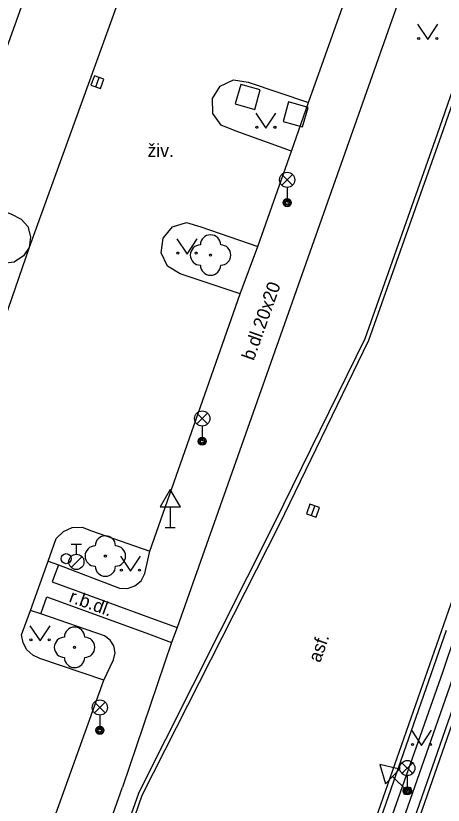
# Model space of a CAD drawing. Extents: x -598932 to -598196, y -1162207 to -1161504.
# Drawn here: x -598625.59 to -598604.5, y -1162150.78 to -1162111.78 of the extents above; entities that cross this region are included whole.
import ezdxf

# ---------------------------------------------------------------- set-up
doc = ezdxf.new("R2010")
doc.units = 0
for name, color, linetype in [('Level 22', 7, 'Continuous'), ('Level 26', 7, 'Continuous'), ('Level 27', 7, 'Continuous'), ('Level 28', 7, 'Continuous'), ('Level 33', 7, 'Continuous'), ('Level 34', 7, 'Continuous'), ('Level 36', 7, 'Continuous'), ('TM - chodniky - VP', 7, 'Continuous'), ('TM - komunikace - VP', 7, 'Continuous'), ('TM - plot dreveny_ kovovy - VP', 7, 'Continuous'), ('TM - popis povrchu', 7, 'Continuous'), ('TM - rozhrani ploch obecne - VP', 7, 'Continuous'), ('TM - svodidlo jednostranne - VP', 7, 'Continuous')]:
    doc.layers.add(name, color=color, linetype=linetype)

msp = doc.modelspace()

# ---------------------------------------------------------------- linework, layer by layer
at = {"layer": 'Level 22'}
for centre in [(-598615.98, -1162123.6), (-598621.17, -1162138.47), (-598622.69, -1162142.98)]:
    msp.add_circle(centre, 0.05, dxfattribs=at)
for centre, start, end in [((-598615.98, -1162123.1), 0, 180), ((-598616.48, -1162123.6), 90, 270), ((-598615.48, -1162123.6), 270, 90), ((-598615.98, -1162124.1), 180, 0), ((-598621.17, -1162137.97), 0, 180), ((-598621.67, -1162138.47), 90, 270), ((-598620.67, -1162138.47), 270, 90), ((-598621.17, -1162138.97), 180, 0), ((-598622.69, -1162142.48), 0, 180), ((-598623.19, -1162142.98), 90, 270), ((-598622.19, -1162142.98), 270, 90), ((-598622.69, -1162143.48), 180, 0)]:
    msp.add_arc(centre, 0.5, start, end, dxfattribs=at)
at = {"layer": 'Level 26'}
for points in [[(-598614.757, -1162116.135), (-598613.795, -1162116.407), (-598613.523, -1162115.445), (-598614.485, -1162115.173)], [(-598612.397, -1162116.995), (-598611.435, -1162117.267), (-598611.163, -1162116.305), (-598612.125, -1162116.033)]]:
    msp.add_lwpolyline(points, close=True, dxfattribs=at)
at = {"layer": 'Level 27'}
for p, q in [((-598621.643, -1162115.296), (-598621.477, -1162114.824)), ((-598611.002, -1162136.466), (-598610.838, -1162135.994))]:
    msp.add_line(p, q, dxfattribs=at)
for points in [[(-598621.408, -1162115.379), (-598621.241, -1162114.908), (-598621.712, -1162114.741), (-598621.879, -1162115.212)], [(-598610.766, -1162136.548), (-598610.602, -1162136.076), (-598611.074, -1162135.912), (-598611.238, -1162136.384)]]:
    msp.add_lwpolyline(points, close=True, dxfattribs=at)
at = {"layer": 'Level 28'}
for p, q in [((-598622.85, -1162137.885), (-598622.35, -1162137.885)), ((-598622.6, -1162138.385), (-598622.6, -1162137.885)), ((-598622.858, -1162139.032), (-598622.328, -1162138.502))]:
    msp.add_line(p, q, dxfattribs=at)
for centre, radius in [((-598623.1, -1162138.6), 0.25), ((-598622.6, -1162138.76), 0.375)]:
    msp.add_circle(centre, radius, dxfattribs=at)
at = {"layer": 'Level 33'}
for p, q in [((-598612.465, -1162120.15), (-598611.935, -1162119.62)), ((-598612.465, -1162119.62), (-598611.935, -1162120.15)), ((-598612.2, -1162120.26), (-598612.2, -1162121.01)), ((-598616.655, -1162131.94), (-598616.125, -1162131.41)), ((-598616.655, -1162131.41), (-598616.125, -1162131.94)), ((-598616.39, -1162132.05), (-598616.39, -1162132.8)), ((-598621.705, -1162146.22), (-598621.175, -1162145.69)), ((-598621.705, -1162145.69), (-598621.175, -1162146.22)), ((-598621.44, -1162146.33), (-598621.44, -1162147.08)), ((-598606.535, -1162149.21), (-598606.005, -1162148.68)), ((-598606.535, -1162148.68), (-598606.005, -1162149.21)), ((-598606.27, -1162149.32), (-598606.27, -1162150.07))]:
    msp.add_line(p, q, dxfattribs=at)
for centre, radius in [((-598612.2, -1162119.885), 0.375), ((-598612.2, -1162121.01), 0.2), ((-598612.2, -1162121.01), 0.145), ((-598612.2, -1162121.01), 0.0876), ((-598616.39, -1162131.675), 0.375), ((-598616.39, -1162132.8), 0.2), ((-598616.39, -1162132.8), 0.145), ((-598616.39, -1162132.8), 0.0876), ((-598621.44, -1162145.955), 0.375), ((-598621.44, -1162147.08), 0.2), ((-598621.44, -1162147.08), 0.145), ((-598621.44, -1162147.08), 0.0876), ((-598606.27, -1162148.945), 0.375), ((-598606.27, -1162150.07), 0.2), ((-598606.27, -1162150.07), 0.145), ((-598606.27, -1162150.07), 0.0876)]:
    msp.add_circle(centre, radius, dxfattribs=at)
at = {"layer": 'Level 34'}
for p, q in [((-598617.97, -1162136.042), (-598617.97, -1162137.06)), ((-598618.22, -1162137.06), (-598617.72, -1162137.06)), ((-598607.006, -1162149.367), (-598606.27, -1162150.07)), ((-598606.443, -1162150.251), (-598606.097, -1162149.889))]:
    msp.add_line(p, q, dxfattribs=at)
for points in [[(-598618.47, -1162136.042), (-598617.47, -1162136.042), (-598617.97, -1162135.176)], [(-598607.352, -1162149.729), (-598606.661, -1162149.005), (-598607.633, -1162148.769)]]:
    msp.add_lwpolyline(points, close=True, dxfattribs=at)
at = {"layer": 'Level 36'}
for points in [[(-598605.76, -1162112.2), (-598605.26, -1162112.95), (-598604.76, -1162112.2)], [(-598613.75, -1162116.59), (-598613.25, -1162117.34), (-598612.75, -1162116.59)], [(-598617.64, -1162122.8), (-598617.14, -1162123.55), (-598616.64, -1162122.8)], [(-598620.43, -1162138.47), (-598619.93, -1162139.22), (-598619.43, -1162138.47)], [(-598624.89, -1162141.91), (-598624.39, -1162142.66), (-598623.89, -1162141.91)], [(-598606.07, -1162147.08), (-598605.57, -1162147.83), (-598605.07, -1162147.08)]]:
    msp.add_lwpolyline(points, dxfattribs=at)
for centre in [(-598605.71, -1162112.9), (-598604.811, -1162112.9), (-598613.7, -1162117.29), (-598612.801, -1162117.29), (-598617.59, -1162123.5), (-598616.691, -1162123.5), (-598620.38, -1162139.17), (-598619.481, -1162139.17), (-598624.84, -1162142.61), (-598623.941, -1162142.61), (-598606.02, -1162147.78), (-598605.121, -1162147.78)]:
    msp.add_circle(centre, 0.05, dxfattribs=at)
at = {"layer": 'TM - chodniky - VP'}
for points in [[(-598596.69, -1162083.41), (-598600.197, -1162092.988), (-598603.83, -1162102.91), (-598607.233, -1162112.549), (-598617.63, -1162142)], [(-598614.47, -1162094.28), (-598618.67, -1162092.86), (-598623.99, -1162107.62), (-598628.55, -1162120.32)], [(-598611.98, -1162118.47), (-598611.15, -1162116.07)], [(-598614.51, -1162125.52), (-598613.65, -1162123.18)], [(-598623.48, -1162138.91), (-598620.48, -1162140.05), (-598620.08, -1162140.08), (-598619.71, -1162139.95), (-598619.41, -1162139.69), (-598619.23, -1162139.34), (-598618.97, -1162138.23)], [(-598623.99, -1162138.72), (-598623.48, -1162138.91)], [(-598624.36, -1162141.33), (-598624.87, -1162141.16)], [(-598621.25, -1162144.6), (-598620.76, -1162143.6), (-598620.69, -1162143.26), (-598620.75, -1162142.91), (-598620.94, -1162142.62), (-598621.22, -1162142.42), (-598624.36, -1162141.33)], [(-598617.63, -1162142), (-598617.9, -1162142.74)], [(-598617.9, -1162142.74), (-598620.33, -1162149.89)]]:
    msp.add_lwpolyline(points, dxfattribs=at)
at = {"layer": 'TM - komunikace - VP'}
for points in [[(-598608.35, -1162127.72), (-598604.78, -1162117.61), (-598598.22, -1162098.74), (-598591.99, -1162080.94)], [(-598614.47, -1162094.28), (-598624.93, -1162123.23)], [(-598611.15, -1162116.07), (-598609.47, -1162111.36)], [(-598611.98, -1162118.47), (-598614.77, -1162117.46), (-598615.45, -1162117.19), (-598615.86, -1162116.6), (-598615.88, -1162115.87), (-598615.5, -1162115.25), (-598614.84, -1162114.95), (-598614.12, -1162115.06), (-598611.15, -1162116.07)], [(-598613.65, -1162123.18), (-598611.98, -1162118.47)], [(-598614.51, -1162125.52), (-598617.48, -1162124.53), (-598618.1, -1162124.15), (-598618.41, -1162123.49), (-598618.32, -1162122.77), (-598617.85, -1162122.21), (-598617.16, -1162122), (-598616.46, -1162122.2), (-598613.65, -1162123.18)], [(-598624.93, -1162123.23), (-598628.91, -1162134.76)], [(-598618.97, -1162138.23), (-598614.51, -1162125.52)], [(-598619.53, -1162150.2), (-598612.81, -1162136.81), (-598608.35, -1162127.72)], [(-598623.99, -1162138.72), (-598623.59, -1162137.6), (-598623.24, -1162137.25), (-598622.8, -1162137.06), (-598622.31, -1162137.04), (-598621.85, -1162137.22), (-598618.97, -1162138.23)], [(-598624.87, -1162141.16), (-598623.99, -1162138.72)], [(-598624.4, -1162143.53), (-598624.75, -1162143.37), (-598625.04, -1162143.1), (-598625.22, -1162142.76), (-598625.3, -1162142.37), (-598624.87, -1162141.16)], [(-598616.67, -1162177.49), (-598609.8, -1162157.81), (-598604.34, -1162142.13)], [(-598624.794, -1162206.96), (-598621.59, -1162196.99), (-598619.16, -1162189.65), (-598615.15, -1162177.92), (-598608.61, -1162159.2), (-598602.85, -1162142.65)], [(-598621.25, -1162144.6), (-598624.4, -1162143.53)], [(-598625.45, -1162156.35), (-598621.25, -1162144.6)], [(-598619.53, -1162150.2), (-598623.67, -1162161.84), (-598626.789, -1162170.612), (-598627.81, -1162173.48)]]:
    msp.add_lwpolyline(points, dxfattribs=at)
at = {"layer": 'TM - plot dreveny_ kovovy - VP'}
msp.add_lwpolyline([(-598625.185, -1162206.96), (-598625, -1162206.36), (-598622.57, -1162198.85), (-598618.79, -1162187.52), (-598616.03, -1162179.39), (-598612.19, -1162168.43), (-598612.14, -1162166.13), (-598608.2, -1162154.66), (-598604.51, -1162144.2), (-598603.87, -1162142.29)], dxfattribs=at)
at = {"layer": 'TM - rozhrani ploch obecne - VP'}
for points in [[(-598608.17, -1162127.81), (-598604.58, -1162117.67), (-598597.99, -1162098.8), (-598591.77, -1162081)], [(-598627.16, -1162121.09), (-598625.83, -1162121.56), (-598625.32, -1162121.82), (-598624.99, -1162122.19), (-598624.86, -1162122.7), (-598624.93, -1162123.23)], [(-598624.93, -1162123.23), (-598625.21, -1162123.64), (-598625.67, -1162123.96), (-598626.21, -1162124.01), (-598626.71, -1162123.87), (-598627.99, -1162123.4)], [(-598619.35, -1162150.29), (-598612.58, -1162136.91), (-598608.17, -1162127.81)], [(-598623.48, -1162138.91), (-598623.79, -1162139.75), (-598618.765, -1162141.585), (-598617.63, -1162142)], [(-598626.703, -1162206.96), (-598626.35, -1162205.84), (-598623.58, -1162197.32), (-598620.04, -1162186.69), (-598616.88, -1162177.43), (-598610.34, -1162158.65), (-598603.78, -1162139.88)], [(-598624.542, -1162206.96), (-598621.37, -1162197.08), (-598617.92, -1162186.71), (-598614.95, -1162178.01), (-598608.42, -1162159.28), (-598601.88, -1162140.55)], [(-598624.36, -1162141.33), (-598624.06, -1162140.49), (-598619.049, -1162142.32), (-598617.9, -1162142.74)], [(-598636.1, -1162186.44), (-598633.63, -1162187.36), (-598633.56, -1162187.15), (-598626.86, -1162168.31), (-598620.33, -1162149.89)], [(-598620.4, -1162153.35), (-598619.35, -1162150.29)]]:
    msp.add_lwpolyline(points, dxfattribs=at)
at = {"layer": 'TM - svodidlo jednostranne - VP'}
msp.add_lwpolyline([(-598603.33, -1162142.48), (-598604.31, -1162145.28), (-598608.44, -1162157.08), (-598610.08, -1162161.8)], dxfattribs=at)

# ---------------------------------------------------------------- texts
at = {"layer": 'TM - popis povrchu'}
msp.add_text('živ.', height=0.65, dxfattribs=at).set_placement((-598619.09, -1162118.76))
for s, rotation, p in [('b.dl.20x20', 70.47, (-598613.85, -1162128.85)), ('r.b.dl.', 339.93, (-598623.01, -1162140.72)), ('asf.', 70.83, (-598610.57, -1162143.77))]:
    msp.add_text(s, height=0.65, rotation=rotation, dxfattribs=at).set_placement(p)

doc.saveas('drawing.dxf')
